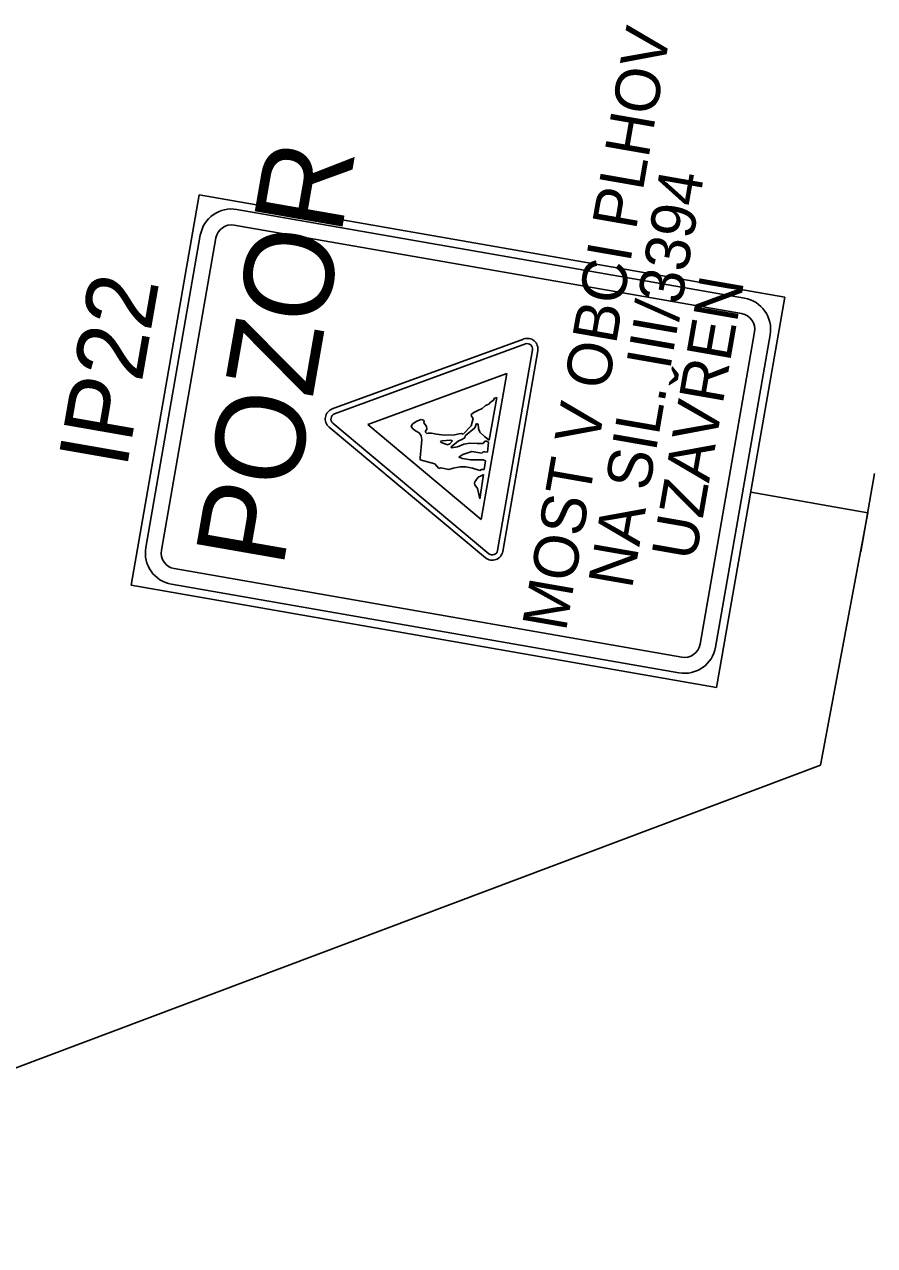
# Model space of a CAD drawing. Extents: x -688893 to -679983, y -1088371 to -1075771.
# Drawn here: x -683465 to -682821, y -1080183 to -1079258 of the extents above; entities that cross this region are included whole.
import ezdxf

# ---------------------------------------------------------------- set-up
doc = ezdxf.new("R2010")
doc.units = 0
for name, color, linetype in [('SDZ', 7, 'Continuous'), ('SDZ ozn', 7, 'Continuous'), ('SDZ plochy', 7, 'Continuous'), ('SDZ symbol', 7, 'Continuous')]:
    doc.layers.add(name, color=color, linetype=linetype)

msp = doc.modelspace()

# ---------------------------------------------------------------- linework, layer by layer
at = {"layer": 'SDZ'}
for p, q in [((-683383.9, -1079682.81), (-683332.33, -1079387.28)), ((-683332.33, -1079387.28), (-682889.03, -1079464.63)), ((-683303.81, -1079398.34), (-682919.62, -1079465.38)), ((-683305.87, -1079410.17), (-682921.68, -1079477.2)), ((-683372.83, -1079654.29), (-683331.58, -1079417.86)), ((-683361.01, -1079656.35), (-683319.76, -1079419.92)), ((-682889.03, -1079464.63), (-682940.6, -1079760.16)), ((-682911.92, -1079491.09), (-682953.18, -1079727.52)), ((-682900.1, -1079493.15), (-682941.35, -1079729.58)), ((-683231.62, -1079549.32), (-683086.79, -1079496.41)), ((-683085.39, -1079500.15), (-683230, -1079553.17)), ((-683106.51, -1079656.53), (-683080.01, -1079504.65)), ((-683102.51, -1079657.16), (-683076.03, -1079505.41)), ((-683099.58, -1079522.54), (-683204.77, -1079561.13)), ((-683118.86, -1079633.06), (-683099.58, -1079522.54)), ((-683112.91, -1079573.05), (-683107.07, -1079540.76)), ((-683107.07, -1079540.76), (-683108.81, -1079541.28)), ((-683231.48, -1079549.27), (-683231.48, -1079549.27)), ((-683118.16, -1079548.9), (-683121.53, -1079550.57)), ((-683115.71, -1079546.66), (-683118.16, -1079548.9)), ((-683113.07, -1079545.68), (-683115.71, -1079546.66)), ((-683111.79, -1079544.26), (-683113.07, -1079545.68)), ((-683109.72, -1079542.97), (-683111.79, -1079544.26)), ((-683108.81, -1079541.28), (-683109.72, -1079542.97)), ((-683167.73, -1079558.55), (-683170.51, -1079560.32)), ((-683164.43, -1079557.27), (-683167.73, -1079558.55)), ((-683162.47, -1079557.82), (-683164.43, -1079557.27)), ((-683162.04, -1079558.92), (-683162.47, -1079557.82)), ((-683162.42, -1079559.88), (-683162.04, -1079558.92)), ((-683125.04, -1079556.54), (-683126.41, -1079562.06)), ((-683124.47, -1079552.12), (-683126.35, -1079553.43)), ((-683126.35, -1079553.43), (-683126.16, -1079554.7)), ((-683126.16, -1079554.7), (-683125.04, -1079556.54)), ((-683121.53, -1079550.57), (-683124.47, -1079552.12)), ((-683115.68, -1079661.98), (-683234.03, -1079563.15)), ((-683231.3, -1079559.99), (-683231.3, -1079559.99)), ((-683231.2, -1079560.08), (-683113.1, -1079658.94)), ((-683204.77, -1079561.13), (-683118.86, -1079633.06)), ((-683170.51, -1079560.32), (-683171.86, -1079562.14)), ((-683171.86, -1079562.14), (-683171.14, -1079563.91)), ((-683171.14, -1079563.91), (-683168.59, -1079565.8)), ((-683168.59, -1079565.8), (-683165.8, -1079567.52)), ((-683165.8, -1079567.52), (-683164.36, -1079569.82)), ((-683161.19, -1079561.13), (-683162.42, -1079559.88)), ((-683160.24, -1079562.73), (-683161.19, -1079561.13)), ((-683161.17, -1079566.89), (-683161.03, -1079566.09)), ((-683160.11, -1079567.89), (-683161.17, -1079566.89)), ((-683161.03, -1079566.09), (-683160.16, -1079564.6)), ((-683160.16, -1079564.6), (-683160.24, -1079562.73)), ((-683159.05, -1079567.67), (-683160.11, -1079567.89)), ((-683156.58, -1079567.69), (-683159.05, -1079567.67)), ((-683152.79, -1079568.35), (-683156.58, -1079567.69)), ((-683146.57, -1079569.23), (-683152.79, -1079568.35)), ((-683135.51, -1079568.28), (-683139.11, -1079568.88)), ((-683133.81, -1079567.96), (-683135.51, -1079568.28)), ((-683132.65, -1079568.37), (-683133.81, -1079567.96)), ((-683126.41, -1079562.06), (-683132.65, -1079568.37)), ((-683131.03, -1079569.68), (-683123.59, -1079563.58)), ((-683123.59, -1079563.58), (-683122.4, -1079560.29)), ((-683122.4, -1079560.29), (-683121.08, -1079560.93)), ((-683121.08, -1079560.93), (-683120.84, -1079564.26)), ((-683120.84, -1079564.26), (-683119.86, -1079566.9)), ((-683119.86, -1079566.9), (-683116.32, -1079570.19)), ((-683163.85, -1079572.79), (-683165.18, -1079586.33)), ((-683164.36, -1079569.82), (-683163.85, -1079572.79)), ((-683148.54, -1079573.41), (-683149.64, -1079573.83)), ((-683149.64, -1079573.83), (-683149.18, -1079574.73)), ((-683149.18, -1079574.73), (-683145.69, -1079575.96)), ((-683145.44, -1079573.33), (-683148.54, -1079573.41)), ((-683139.11, -1079568.88), (-683146.57, -1079569.23)), ((-683145.69, -1079575.96), (-683144.33, -1079576.4)), ((-683142.11, -1079573.09), (-683145.44, -1079573.33)), ((-683144.33, -1079576.4), (-683142.56, -1079575.68)), ((-683142.56, -1079575.68), (-683140.51, -1079573.37)), ((-683140.51, -1079573.37), (-683142.11, -1079573.09)), ((-683141.78, -1079578.29), (-683136.02, -1079573.54)), ((-683131.91, -1079575.9), (-683136.82, -1079578.12)), ((-683136.02, -1079573.54), (-683134.02, -1079572.65)), ((-683134.02, -1079572.65), (-683131.31, -1079571.27)), ((-683127.48, -1079575.23), (-683131.91, -1079575.9)), ((-683131.31, -1079571.27), (-683131.03, -1079569.68)), ((-683121.99, -1079575.57), (-683127.48, -1079575.23)), ((-683117.26, -1079575.58), (-683121.99, -1079575.57)), ((-683116.11, -1079573.72), (-683117.26, -1079575.58)), ((-683116.32, -1079570.19), (-683112.91, -1079573.05)), ((-683114.88, -1079573.73), (-683116.11, -1079573.72)), ((-683113.36, -1079574.41), (-683114.88, -1079573.73)), ((-683114.08, -1079582.09), (-683113.36, -1079574.41)), ((-683165.18, -1079586.33), (-683165.03, -1079587.8)), ((-683141.45, -1079578.75), (-683141.78, -1079578.29)), ((-683136.82, -1079578.12), (-683141.45, -1079578.75)), ((-683135.91, -1079585.89), (-683132.9, -1079583.95)), ((-683132.99, -1079586.81), (-683135.91, -1079585.89)), ((-683127.01, -1079587.85), (-683132.99, -1079586.81)), ((-683132.9, -1079583.95), (-683127.43, -1079582.02)), ((-683127.43, -1079582.02), (-683125.89, -1079581.47)), ((-683125.89, -1079581.47), (-683118.51, -1079582.76)), ((-683118.51, -1079582.76), (-683117.31, -1079581.73)), ((-683117.31, -1079581.73), (-683116.27, -1079581.71)), ((-683116.27, -1079581.71), (-683114.08, -1079582.09)), ((-683165.03, -1079587.8), (-683153.86, -1079590.98)), ((-683153.86, -1079590.98), (-683150.96, -1079594.36)), ((-683150.96, -1079594.36), (-683149.42, -1079593.81)), ((-683149.42, -1079593.81), (-683143.28, -1079595.09)), ((-683143.28, -1079595.09), (-683140.04, -1079594.21)), ((-683140.04, -1079594.21), (-683134.9, -1079593.05)), ((-683134.9, -1079593.05), (-683130.41, -1079593.22)), ((-683130.41, -1079593.22), (-683125.46, -1079594.29)), ((-683117.35, -1079587.89), (-683127.01, -1079587.85)), ((-683125.46, -1079594.29), (-683120.01, -1079596.06)), ((-683120.01, -1079596.06), (-683118.61, -1079595.07)), ((-683118.61, -1079595.07), (-683116.58, -1079595.22)), ((-683115.63, -1079588.61), (-683117.35, -1079587.89)), ((-683116.58, -1079595.22), (-683115.63, -1079588.61)), ((-683123.74, -1079604.46), (-683123.95, -1079605.65)), ((-683122.97, -1079603.56), (-683123.74, -1079604.46)), ((-683121.08, -1079601.01), (-683122.97, -1079603.56)), ((-683118.84, -1079599.97), (-683121.08, -1079601.01)), ((-683119.84, -1079617.47), (-683117.04, -1079599.05)), ((-683117.04, -1079599.05), (-683118.84, -1079599.97)), ((-682831.31, -1079657.42), (-682821, -1079598.31)), ((-683123.95, -1079605.65), (-683123.72, -1079606.72)), ((-683123.72, -1079606.72), (-683121.55, -1079609.57)), ((-683121.55, -1079609.57), (-683120.87, -1079612.77)), ((-683120.87, -1079612.77), (-683119.84, -1079617.47)), ((-682914.82, -1079612.4), (-682826.16, -1079627.87)), ((-682967.06, -1079737.28), (-683351.25, -1079670.24)), ((-682940.6, -1079760.16), (-683383.9, -1079682.81)), ((-682969.12, -1079749.1), (-683353.32, -1079682.06))]:
    msp.add_line(p, q, dxfattribs=at)
msp.add_lwpolyline([(-683828.78, -1080182.62), (-682861.97, -1079818.86), (-682826.16, -1079627.87)], dxfattribs=at)
for centre, radius, start, end in [((-683307.94, -1079421.99), 24, 80.10201, 170.10201), ((-683307.94, -1079421.99), 12, 80.10201, 170.10201), ((-682923.74, -1079489.03), 24, 350.10201, 80.10201), ((-682923.74, -1079489.03), 12, 350.10201, 80.10201), ((-683084.01, -1079504.01), 8.1, 350.10201, 110.07111), ((-683084, -1079503.95), 4.05, 350.10201, 110.13631), ((-683228.84, -1079556.93), 8.1, 110.07111, 230.13292), ((-683228.6, -1079556.97), 4.05, 110.13631, 230.06772), ((-683349.19, -1079658.42), 24, 170.10201, 260.10201), ((-683349.19, -1079658.42), 12, 170.10201, 260.10201), ((-683110.49, -1079655.77), 8.1, 230.13292, 350.10201), ((-683110.5, -1079655.83), 4.05, 230.06772, 350.10201), ((-682965, -1079725.45), 24, 260.10201, 350.10201), ((-682965, -1079725.45), 12, 260.10201, 350.10201)]:
    msp.add_arc(centre, radius, start, end, dxfattribs=at)
at = {"layer": 'SDZ plochy'}
for p, q in [((-683332.33, -1079387.28), (-683383.9, -1079682.81)), ((-682889.03, -1079464.63), (-683332.33, -1079387.28)), ((-682919.62, -1079465.38), (-683303.81, -1079398.34)), ((-683303.81, -1079398.34), (-682919.62, -1079465.38)), ((-683305.87, -1079410.17), (-682921.68, -1079477.2)), ((-682921.68, -1079477.2), (-683305.87, -1079410.17)), ((-683331.58, -1079417.86), (-683372.83, -1079654.29)), ((-683372.83, -1079654.29), (-683331.58, -1079417.86)), ((-683361.01, -1079656.35), (-683319.76, -1079419.92)), ((-683319.76, -1079419.92), (-683361.01, -1079656.35)), ((-682940.6, -1079760.16), (-682889.03, -1079464.63)), ((-682911.92, -1079491.09), (-682953.18, -1079727.52)), ((-682953.18, -1079727.52), (-682911.92, -1079491.09)), ((-682941.35, -1079729.58), (-682900.1, -1079493.15)), ((-682900.1, -1079493.15), (-682941.35, -1079729.58)), ((-683231.62, -1079549.32), (-683086.79, -1079496.41)), ((-683086.79, -1079496.41), (-683231.62, -1079549.32)), ((-683085.39, -1079500.15), (-683230, -1079553.17)), ((-683230, -1079553.17), (-683085.39, -1079500.15)), ((-683106.51, -1079656.53), (-683080.01, -1079504.65)), ((-683080.01, -1079504.65), (-683106.51, -1079656.53)), ((-683076.03, -1079505.41), (-683102.51, -1079657.16)), ((-683102.51, -1079657.16), (-683076.03, -1079505.41)), ((-683204.77, -1079561.13), (-683099.58, -1079522.54)), ((-683099.58, -1079522.54), (-683204.77, -1079561.13)), ((-683099.58, -1079522.54), (-683118.86, -1079633.06)), ((-683118.86, -1079633.06), (-683099.58, -1079522.54)), ((-683112.91, -1079573.05), (-683107.07, -1079540.76)), ((-683107.07, -1079540.76), (-683112.91, -1079573.05)), ((-683107.07, -1079540.76), (-683108.81, -1079541.28)), ((-683108.81, -1079541.28), (-683107.07, -1079540.76)), ((-683118.16, -1079548.9), (-683121.53, -1079550.57)), ((-683121.53, -1079550.57), (-683118.16, -1079548.9)), ((-683115.71, -1079546.66), (-683118.16, -1079548.9)), ((-683118.16, -1079548.9), (-683115.71, -1079546.66)), ((-683113.07, -1079545.68), (-683115.71, -1079546.66)), ((-683115.71, -1079546.66), (-683113.07, -1079545.68)), ((-683111.79, -1079544.26), (-683113.07, -1079545.68)), ((-683113.07, -1079545.68), (-683111.79, -1079544.26)), ((-683109.72, -1079542.97), (-683111.79, -1079544.26)), ((-683111.79, -1079544.26), (-683109.72, -1079542.97)), ((-683108.81, -1079541.28), (-683109.72, -1079542.97)), ((-683109.72, -1079542.97), (-683108.81, -1079541.28)), ((-683167.73, -1079558.55), (-683170.51, -1079560.32)), ((-683170.51, -1079560.32), (-683167.73, -1079558.55)), ((-683164.43, -1079557.27), (-683167.73, -1079558.55)), ((-683167.73, -1079558.55), (-683164.43, -1079557.27)), ((-683162.47, -1079557.82), (-683164.43, -1079557.27)), ((-683164.43, -1079557.27), (-683162.47, -1079557.82)), ((-683162.04, -1079558.92), (-683162.47, -1079557.82)), ((-683162.47, -1079557.82), (-683162.04, -1079558.92)), ((-683162.42, -1079559.88), (-683162.04, -1079558.92)), ((-683162.04, -1079558.92), (-683162.42, -1079559.88)), ((-683125.04, -1079556.54), (-683126.41, -1079562.06)), ((-683126.41, -1079562.06), (-683125.04, -1079556.54)), ((-683124.47, -1079552.12), (-683126.35, -1079553.43)), ((-683126.35, -1079553.43), (-683124.47, -1079552.12)), ((-683126.35, -1079553.43), (-683126.16, -1079554.7)), ((-683126.16, -1079554.7), (-683126.35, -1079553.43)), ((-683126.16, -1079554.7), (-683125.04, -1079556.54)), ((-683125.04, -1079556.54), (-683126.16, -1079554.7)), ((-683121.53, -1079550.57), (-683124.47, -1079552.12)), ((-683124.47, -1079552.12), (-683121.53, -1079550.57)), ((-683115.68, -1079661.98), (-683234.03, -1079563.15)), ((-683234.03, -1079563.15), (-683115.68, -1079661.98)), ((-683231.2, -1079560.08), (-683113.1, -1079658.94)), ((-683113.1, -1079658.94), (-683231.2, -1079560.08)), ((-683118.86, -1079633.06), (-683204.77, -1079561.13)), ((-683204.77, -1079561.13), (-683118.86, -1079633.06)), ((-683170.51, -1079560.32), (-683171.86, -1079562.14)), ((-683171.86, -1079562.14), (-683170.51, -1079560.32)), ((-683171.86, -1079562.14), (-683171.14, -1079563.91)), ((-683171.14, -1079563.91), (-683171.86, -1079562.14)), ((-683171.14, -1079563.91), (-683168.59, -1079565.8)), ((-683168.59, -1079565.8), (-683171.14, -1079563.91)), ((-683168.59, -1079565.8), (-683165.8, -1079567.52)), ((-683165.8, -1079567.52), (-683168.59, -1079565.8)), ((-683165.8, -1079567.52), (-683164.36, -1079569.82)), ((-683164.36, -1079569.82), (-683165.8, -1079567.52)), ((-683161.19, -1079561.13), (-683162.42, -1079559.88)), ((-683162.42, -1079559.88), (-683161.19, -1079561.13)), ((-683160.24, -1079562.73), (-683161.19, -1079561.13)), ((-683161.19, -1079561.13), (-683160.24, -1079562.73)), ((-683161.17, -1079566.89), (-683161.03, -1079566.09)), ((-683161.03, -1079566.09), (-683161.17, -1079566.89)), ((-683160.11, -1079567.89), (-683161.17, -1079566.89)), ((-683161.17, -1079566.89), (-683160.11, -1079567.89)), ((-683161.03, -1079566.09), (-683160.16, -1079564.6)), ((-683160.16, -1079564.6), (-683161.03, -1079566.09)), ((-683160.16, -1079564.6), (-683160.24, -1079562.73)), ((-683160.24, -1079562.73), (-683160.16, -1079564.6)), ((-683159.05, -1079567.67), (-683160.11, -1079567.89)), ((-683160.11, -1079567.89), (-683159.05, -1079567.67)), ((-683156.58, -1079567.69), (-683159.05, -1079567.67)), ((-683159.05, -1079567.67), (-683156.58, -1079567.69)), ((-683152.79, -1079568.35), (-683156.58, -1079567.69)), ((-683156.58, -1079567.69), (-683152.79, -1079568.35)), ((-683146.57, -1079569.23), (-683152.79, -1079568.35)), ((-683152.79, -1079568.35), (-683146.57, -1079569.23)), ((-683135.51, -1079568.28), (-683139.11, -1079568.88)), ((-683139.11, -1079568.88), (-683135.51, -1079568.28)), ((-683133.81, -1079567.96), (-683135.51, -1079568.28)), ((-683135.51, -1079568.28), (-683133.81, -1079567.96)), ((-683132.65, -1079568.37), (-683133.81, -1079567.96)), ((-683133.81, -1079567.96), (-683132.65, -1079568.37)), ((-683126.41, -1079562.06), (-683132.65, -1079568.37)), ((-683132.65, -1079568.37), (-683126.41, -1079562.06)), ((-683131.03, -1079569.68), (-683123.59, -1079563.58)), ((-683123.59, -1079563.58), (-683131.03, -1079569.68)), ((-683123.59, -1079563.58), (-683122.4, -1079560.29)), ((-683122.4, -1079560.29), (-683123.59, -1079563.58)), ((-683122.4, -1079560.29), (-683121.08, -1079560.93)), ((-683121.08, -1079560.93), (-683122.4, -1079560.29)), ((-683121.08, -1079560.93), (-683120.84, -1079564.26)), ((-683120.84, -1079564.26), (-683121.08, -1079560.93)), ((-683120.84, -1079564.26), (-683119.86, -1079566.9)), ((-683119.86, -1079566.9), (-683120.84, -1079564.26)), ((-683119.86, -1079566.9), (-683116.32, -1079570.19)), ((-683116.32, -1079570.19), (-683119.86, -1079566.9)), ((-683163.85, -1079572.79), (-683165.18, -1079586.33)), ((-683165.18, -1079586.33), (-683163.85, -1079572.79)), ((-683164.36, -1079569.82), (-683163.85, -1079572.79)), ((-683163.85, -1079572.79), (-683164.36, -1079569.82)), ((-683149.64, -1079573.83), (-683148.54, -1079573.41)), ((-683148.54, -1079573.41), (-683149.64, -1079573.83)), ((-683149.18, -1079574.73), (-683149.64, -1079573.83)), ((-683149.64, -1079573.83), (-683149.18, -1079574.73)), ((-683145.69, -1079575.96), (-683149.18, -1079574.73)), ((-683149.18, -1079574.73), (-683145.69, -1079575.96)), ((-683148.54, -1079573.41), (-683145.44, -1079573.33)), ((-683145.44, -1079573.33), (-683148.54, -1079573.41)), ((-683139.11, -1079568.88), (-683146.57, -1079569.23)), ((-683146.57, -1079569.23), (-683139.11, -1079568.88)), ((-683144.33, -1079576.4), (-683145.69, -1079575.96)), ((-683145.69, -1079575.96), (-683144.33, -1079576.4)), ((-683145.44, -1079573.33), (-683142.11, -1079573.09)), ((-683142.11, -1079573.09), (-683145.44, -1079573.33)), ((-683142.56, -1079575.68), (-683144.33, -1079576.4)), ((-683144.33, -1079576.4), (-683142.56, -1079575.68)), ((-683140.51, -1079573.37), (-683142.56, -1079575.68)), ((-683142.56, -1079575.68), (-683140.51, -1079573.37)), ((-683142.11, -1079573.09), (-683140.51, -1079573.37)), ((-683140.51, -1079573.37), (-683142.11, -1079573.09)), ((-683141.78, -1079578.29), (-683136.02, -1079573.54)), ((-683136.02, -1079573.54), (-683141.78, -1079578.29)), ((-683131.91, -1079575.9), (-683136.82, -1079578.12)), ((-683136.82, -1079578.12), (-683131.91, -1079575.9)), ((-683136.02, -1079573.54), (-683134.02, -1079572.65)), ((-683134.02, -1079572.65), (-683136.02, -1079573.54)), ((-683134.02, -1079572.65), (-683131.31, -1079571.27)), ((-683131.31, -1079571.27), (-683134.02, -1079572.65)), ((-683127.48, -1079575.23), (-683131.91, -1079575.9)), ((-683131.91, -1079575.9), (-683127.48, -1079575.23)), ((-683131.31, -1079571.27), (-683131.03, -1079569.68)), ((-683131.03, -1079569.68), (-683131.31, -1079571.27)), ((-683121.99, -1079575.57), (-683127.48, -1079575.23)), ((-683127.48, -1079575.23), (-683121.99, -1079575.57)), ((-683117.26, -1079575.58), (-683121.99, -1079575.57)), ((-683121.99, -1079575.57), (-683117.26, -1079575.58)), ((-683116.11, -1079573.72), (-683117.26, -1079575.58)), ((-683117.26, -1079575.58), (-683116.11, -1079573.72)), ((-683116.32, -1079570.19), (-683112.91, -1079573.05)), ((-683112.91, -1079573.05), (-683116.32, -1079570.19)), ((-683114.88, -1079573.73), (-683116.11, -1079573.72)), ((-683116.11, -1079573.72), (-683114.88, -1079573.73)), ((-683113.36, -1079574.41), (-683114.88, -1079573.73)), ((-683114.88, -1079573.73), (-683113.36, -1079574.41)), ((-683114.08, -1079582.09), (-683113.36, -1079574.41)), ((-683113.36, -1079574.41), (-683114.08, -1079582.09)), ((-683165.18, -1079586.33), (-683165.03, -1079587.8)), ((-683165.03, -1079587.8), (-683165.18, -1079586.33)), ((-683141.45, -1079578.75), (-683141.78, -1079578.29)), ((-683141.78, -1079578.29), (-683141.45, -1079578.75)), ((-683136.82, -1079578.12), (-683141.45, -1079578.75)), ((-683141.45, -1079578.75), (-683136.82, -1079578.12)), ((-683135.91, -1079585.89), (-683132.9, -1079583.95)), ((-683132.9, -1079583.95), (-683135.91, -1079585.89)), ((-683132.99, -1079586.81), (-683135.91, -1079585.89)), ((-683135.91, -1079585.89), (-683132.99, -1079586.81)), ((-683127.01, -1079587.85), (-683132.99, -1079586.81)), ((-683132.99, -1079586.81), (-683127.01, -1079587.85)), ((-683132.9, -1079583.95), (-683127.43, -1079582.02)), ((-683127.43, -1079582.02), (-683132.9, -1079583.95)), ((-683127.43, -1079582.02), (-683125.89, -1079581.47)), ((-683125.89, -1079581.47), (-683127.43, -1079582.02)), ((-683125.89, -1079581.47), (-683118.51, -1079582.76)), ((-683118.51, -1079582.76), (-683125.89, -1079581.47)), ((-683118.51, -1079582.76), (-683117.31, -1079581.73)), ((-683117.31, -1079581.73), (-683118.51, -1079582.76)), ((-683117.31, -1079581.73), (-683116.27, -1079581.71)), ((-683116.27, -1079581.71), (-683117.31, -1079581.73)), ((-683116.27, -1079581.71), (-683114.08, -1079582.09)), ((-683114.08, -1079582.09), (-683116.27, -1079581.71)), ((-683165.03, -1079587.8), (-683153.86, -1079590.98)), ((-683153.86, -1079590.98), (-683165.03, -1079587.8)), ((-683153.86, -1079590.98), (-683150.96, -1079594.36)), ((-683150.96, -1079594.36), (-683153.86, -1079590.98)), ((-683150.96, -1079594.36), (-683149.42, -1079593.81)), ((-683149.42, -1079593.81), (-683150.96, -1079594.36)), ((-683149.42, -1079593.81), (-683143.28, -1079595.09)), ((-683143.28, -1079595.09), (-683149.42, -1079593.81)), ((-683143.28, -1079595.09), (-683140.04, -1079594.21)), ((-683140.04, -1079594.21), (-683143.28, -1079595.09)), ((-683140.04, -1079594.21), (-683134.9, -1079593.05)), ((-683134.9, -1079593.05), (-683140.04, -1079594.21)), ((-683134.9, -1079593.05), (-683130.41, -1079593.22)), ((-683130.41, -1079593.22), (-683134.9, -1079593.05)), ((-683130.41, -1079593.22), (-683125.46, -1079594.29)), ((-683125.46, -1079594.29), (-683130.41, -1079593.22)), ((-683117.35, -1079587.89), (-683127.01, -1079587.85)), ((-683127.01, -1079587.85), (-683117.35, -1079587.89)), ((-683125.46, -1079594.29), (-683120.01, -1079596.06)), ((-683120.01, -1079596.06), (-683125.46, -1079594.29)), ((-683120.01, -1079596.06), (-683118.61, -1079595.07)), ((-683118.61, -1079595.07), (-683120.01, -1079596.06)), ((-683118.61, -1079595.07), (-683116.58, -1079595.22)), ((-683116.58, -1079595.22), (-683118.61, -1079595.07)), ((-683115.63, -1079588.61), (-683117.35, -1079587.89)), ((-683117.35, -1079587.89), (-683115.63, -1079588.61)), ((-683116.58, -1079595.22), (-683115.63, -1079588.61)), ((-683115.63, -1079588.61), (-683116.58, -1079595.22)), ((-683123.74, -1079604.46), (-683123.95, -1079605.65)), ((-683123.95, -1079605.65), (-683123.74, -1079604.46)), ((-683122.97, -1079603.56), (-683123.74, -1079604.46)), ((-683123.74, -1079604.46), (-683122.97, -1079603.56)), ((-683121.08, -1079601.01), (-683122.97, -1079603.56)), ((-683122.97, -1079603.56), (-683121.08, -1079601.01)), ((-683118.84, -1079599.97), (-683121.08, -1079601.01)), ((-683121.08, -1079601.01), (-683118.84, -1079599.97)), ((-683119.84, -1079617.47), (-683117.04, -1079599.05)), ((-683117.04, -1079599.05), (-683119.84, -1079617.47)), ((-683117.04, -1079599.05), (-683118.84, -1079599.97)), ((-683118.84, -1079599.97), (-683117.04, -1079599.05)), ((-683123.95, -1079605.65), (-683123.72, -1079606.72)), ((-683123.72, -1079606.72), (-683123.95, -1079605.65)), ((-683123.72, -1079606.72), (-683121.55, -1079609.57)), ((-683121.55, -1079609.57), (-683123.72, -1079606.72)), ((-683121.55, -1079609.57), (-683120.87, -1079612.77)), ((-683120.87, -1079612.77), (-683121.55, -1079609.57)), ((-683120.87, -1079612.77), (-683119.84, -1079617.47)), ((-683119.84, -1079617.47), (-683120.87, -1079612.77)), ((-682967.06, -1079737.28), (-683351.25, -1079670.24)), ((-683351.25, -1079670.24), (-682967.06, -1079737.28)), ((-683383.9, -1079682.81), (-682940.6, -1079760.16)), ((-683353.32, -1079682.06), (-682969.12, -1079749.1)), ((-682969.12, -1079749.1), (-683353.32, -1079682.06))]:
    msp.add_line(p, q, dxfattribs=at)
for centre, radius, start, end in [((-683307.94, -1079421.99), 24, 80.10201, 170.10201), ((-683307.94, -1079421.99), 24, 80.10201, 170.10201), ((-683307.94, -1079421.99), 12, 80.10201, 170.10201), ((-683307.94, -1079421.99), 12, 80.10201, 170.10201), ((-682923.74, -1079489.03), 24, 350.10201, 80.10201), ((-682923.74, -1079489.03), 24, 350.10201, 80.10201), ((-682923.74, -1079489.03), 12, 350.10201, 80.10201), ((-682923.74, -1079489.03), 12, 350.10201, 80.10201), ((-683084.01, -1079504.01), 8.1, 350.10201, 110.07111), ((-683084.01, -1079504.01), 8.1, 350.10201, 110.07111), ((-683084, -1079503.95), 4.05, 350.10201, 110.13631), ((-683084, -1079503.95), 4.05, 350.10201, 110.13631), ((-683228.84, -1079556.93), 8.1, 110.07111, 230.13292), ((-683228.84, -1079556.93), 8.1, 110.07111, 230.13292), ((-683228.6, -1079556.97), 4.05, 110.13631, 230.06772), ((-683228.6, -1079556.97), 4.05, 110.13631, 230.06772), ((-683349.19, -1079658.42), 24, 170.10201, 260.10201), ((-683349.19, -1079658.42), 24, 170.10201, 260.10201), ((-683349.19, -1079658.42), 12, 170.10201, 260.10201), ((-683349.19, -1079658.42), 12, 170.10201, 260.10201), ((-683110.49, -1079655.77), 8.1, 230.13292, 350.10201), ((-683110.49, -1079655.77), 8.1, 230.13292, 350.10201), ((-683110.5, -1079655.83), 4.05, 230.06772, 350.10201), ((-683110.5, -1079655.83), 4.05, 230.06772, 350.10201), ((-682965, -1079725.45), 24, 260.10201, 350.10201), ((-682965, -1079725.45), 24, 260.10201, 350.10201), ((-682965, -1079725.45), 12, 260.10201, 350.10201), ((-682965, -1079725.45), 12, 260.10201, 350.10201)]:
    msp.add_arc(centre, radius, start, end, dxfattribs=at)

# ---------------------------------------------------------------- texts
at = {"layer": 'SDZ ozn'}
msp.add_text('IP22', height=52.5, rotation=80.10201, dxfattribs=at).set_placement((-683387.4, -1079595.32))
at = {"layer": 'SDZ symbol'}
for s, height, p in [('MOST V OBCI PLHOV', 33.75, (-683054.77, -1079718.46)), ('POZOR', 67.5, (-683269.09, -1079670.57)), ('NA SIL. III/3394', 33.75, (-683004.8, -1079686.24)), ('UZAVŘEN', 33.75, (-682956.78, -1079665.11))]:
    msp.add_text(s, height=height, rotation=80.10201, dxfattribs=at).set_placement(p)

doc.saveas('drawing.dxf')
